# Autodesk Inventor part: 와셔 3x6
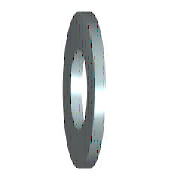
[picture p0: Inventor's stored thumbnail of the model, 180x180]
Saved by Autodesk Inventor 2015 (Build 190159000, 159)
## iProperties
IsCustomPart: 0
Created: 2012-02
Part Number: 와셔 3x6
Material: 강철, 연강
Description: 평면 와셔
Document SubType Name: Modeling
Standard: KS B 1326
Designer: mduedu
Standards Organization: KS
Language: ko-KR
Size Designation: 3x6
Categories: <MemberInstance><Categories><Category DisplayName="조임쇠" InternalName="e4da775c-781d-43d5-af7c-5136215cf5a6" Mnemonic="FSTN"><Category DisplayName="와셔" InternalN
Density: 7.86 g/cm^3
Mass: 0.0795112 g
Surface Area: 0.54915 cm^2
Volume: 0.0101159 cm^3
Appearance: 파란색 - 벽 페인트 - 광택
Author: mduedu
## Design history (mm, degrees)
sketch "스케치"
  geometry: C1 r 3 at (0, 0); C2 r 1.6 at (0, 0); 1 further point
  constraints: 2 centre point, 2 coincident
  dimensions: "d0" = 3.2 diameter of C2 (= SD1); "d1" = 6 diameter of C1 (= SD2)
extrude "본체" new body sketch "스케치" distance "d2" = 0.5 (= SD); taper "d3" = 0 deg
workaxis "Work Axis1"
workplane "Work Plane1"
body "Solid1"
other parameters: "SD1" = 3.2 [user parameter; used in 1 equation term], "SD2" = 6 [user parameter; used in 1 equation term], "SD" = 0.5 [user parameter; used in 1 equation term], "d4" = 0, "d5" = 0, "d6" = 0, "d7" = 0, "NND" = 3 [user parameter]
